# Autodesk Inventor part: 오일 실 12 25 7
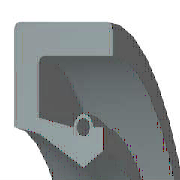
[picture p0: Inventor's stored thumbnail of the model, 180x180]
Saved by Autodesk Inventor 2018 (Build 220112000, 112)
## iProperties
IsCustomPart: 1
Created: 2012-02
Part Number: 오일 실 12 25 7
Material: 고무
Description: 오일-실
Document SubType Name: Modeling
Standard: KS B 2804
Designer: mduedu
Standards Organization: KS
Language: ko-KR
Size Designation: S - 12 25 7
Categories: <MemberInstance><Categories><Category DisplayName="샤프트 부품" InternalName="7f7aeb1f-a693-4053-b835-cee3144e0d98" Mnemonic="SHFT"><Category DisplayName="실링" Intern
Density: 0.93 g/cm^3
Appearance: 고무 - 검은색 - 버전 1.1
Mass: 1.26338 g
Surface Area: 20.8889 cm^2
Volume: 1.35847 cm^3
Author: mduedu
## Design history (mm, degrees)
revolve "본체" stored, may be unused: angle "d17" = 90 deg
revolve "스프링1" stored, may be unused: angle "d18" = 90 deg
body "Solid1"
sketch "스케치1"
  geometry: L1 (0, 12.5)-(7, 12.5); L2 (7, 12.5)-(7, 11.25); L3 (7, 11.25)-(1.75, 11.25); L4 (0, 12.5)-(0, 8.1); L5 (0, 8.1)-(1.75, 7.75); L6 (1.75, 7.75)-(4.9, 6); L7 (4.9, 6)-(0, 6); L8 (6.3, 6.875)-(6.3, 8.1); L9 (0, 0)-(9.586, 0) reference; L10 (4.9, 6)-(6.3, 6.875); L11 (0, 18)-(0, -3) reference; L12 (-1.917, 0)-(11.503, 0) reference; L13 (4.2, 8.1)-(1.75, 8.59); L14 (1.75, 8.59)-(1.75, 11.25); L15 (6.3, 8.1)-(5.6, 8.1); C1 r 0.455 at (4.9, 8.1); A1 r 0.7 centre (4.9, 8.1) between (5.6, 8.1) and (4.2, 8.1)
  constraints: 26 end point, 5 horizontal alignment, 4 perpendicular, 2 centre point, 2 collinear, 2 horizontal, 2 parallel, 2 point on circle, 2 point on line, 2 vertical alignment, 1 coincident
  dimensions: "d0" = 25 diameter of L1 L9 (= SD2); "d1" = 13.75 diameter of L8.start L9 (= ABDM); "d2" = 1.25 distance of L1.end L2.end (computed from SD); "d3" = 0.91 diameter of C1 (= SPDI); "d4" = 1.4 diameter of A1 (= SPDA); "d5" = 12 diameter of L6.end L9 (= NND); "d6" = 15.5 diameter of L5.end L9 (= TKDM); "d7" = 16.2 diameter of L4.end L9 (= HLDM); "d8" = 4.9 distance from line of C1.centre L4 (= SPDST); "d9" = 6.3 distance between parallel lines of L8 L4 (= SDI); "d10" = 7 distance between parallel lines of L2 L4 (= SWDT); "d12" = 1.75 distance between parallel lines of L14 L4 (= SD)
fillet "모깎기1" dims "d11" = 0.3 (= RR)
other parameters: "SD2" = 25 [user parameter; used in 1 equation term], "SWDT" = 7 [user parameter; used in 1 equation term], "RR" = 0.3 [user parameter; used in 1 equation term], "SD" = 1.75 [user parameter; used in 2 equation terms], "NND" = 12 [user parameter; used in 1 equation term], "SPDA" = 1.4 [user parameter; used in 1 equation term], "SPDI" = 0.91 [user parameter; used in 1 equation term], "TKDM" = 15.5 [user parameter; used in 1 equation term], "HLDM" = 16.2 [user parameter; used in 1 equation term], "ABDM" = 13.75 [user parameter; used in 1 equation term], "SDI" = 6.3 [user parameter; used in 1 equation term], "SPDST" = 4.9 [user parameter; used in 1 equation term], "d13" = 0, "d14" = 0, "d15" = 0, "LAB" = 0.35 [user parameter]
